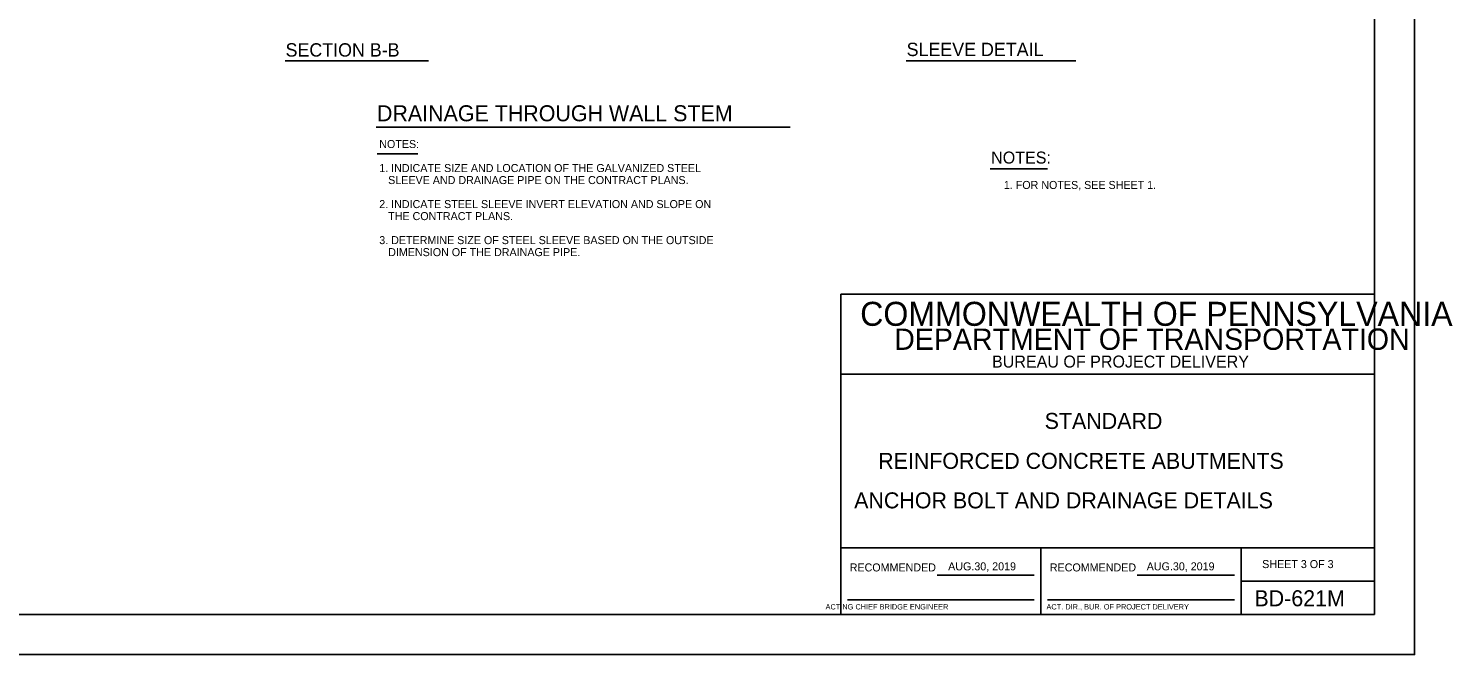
# Model space of a CAD drawing. Extents: x 235 to 2276, y 116 to 1308.
# Drawn here: x 1742 to 2276, y 710 to 945 of the extents above; entities that cross this region are included whole.
import ezdxf

# ---------------------------------------------------------------- set-up
doc = ezdxf.new("R2010")
doc.units = 0
doc.layers.add('1', color=7, linetype='Continuous')
doc.layers.add('PLT-BNDY', color=7, linetype='Continuous')

msp = doc.modelspace()

# ---------------------------------------------------------------- linework, layer by layer
at = {"layer": '1'}
for p, q in [((2246.42, 1289.41), (2246.42, 725.41)), ((1838.13, 932.78), (1891.85, 932.78)), ((2070.9, 932.78), (2134.5, 932.78)), ((1872.24, 907.91), (2027.46, 907.91)), ((1872.72, 897.95), (1887.85, 897.95)), ((2102.37, 892.39), (2123.91, 892.39)), ((2246.42, 845.41), (2046.42, 845.41)), ((2046.42, 845.41), (2046.42, 725.41)), ((2246.42, 725.41), (2246.42, 845.41)), ((2246.42, 815.41), (2046.42, 815.41)), ((2246.42, 750.41), (2046.42, 750.41)), ((2121.42, 725.41), (2121.42, 750.41)), ((2196.42, 750.41), (2196.42, 725.41)), ((2082.51, 740.13), (2118.92, 740.13)), ((2157.51, 740.13), (2193.92, 740.13)), ((2196.42, 737.91), (2246.42, 737.91)), ((2048.92, 730.91), (2118.92, 730.91)), ((2123.92, 730.91), (2193.92, 730.91)), ((2246.42, 725.41), (1460.42, 725.41)), ((2046.42, 725.41), (2246.42, 725.41))]:
    msp.add_line(p, q, dxfattribs=at)
at = {"layer": 'PLT-BNDY'}
msp.add_lwpolyline([(1420.42, 1304.41), (2261.42, 1304.41), (2261.42, 710.41), (1420.42, 710.41)], close=True, dxfattribs=at)

# ---------------------------------------------------------------- texts
at = {"layer": '1'}
for s, height, p in [('SECTION B-B', 5, (1838.33, 934.41)), ('SLEEVE DETAIL', 5, (2071.08, 934.6)), ('DRAINAGE THROUGH WALL STEM', 6, (1872.58, 910.17)), ('NOTES:', 3, (1873.44, 900.15)), ('NOTES:', 4.5, (2102.75, 894.33)), ('1. INDICATE SIZE AND LOCATION OF THE GALVANIZED STEEL', 3, (1873.44, 891.15)), ('   SLEEVE AND DRAINAGE PIPE ON THE CONTRACT PLANS.', 3, (1873.44, 886.65)), ('1. FOR NOTES, SEE SHEET 1.', 3, (2107.51, 884.82)), ('2. INDICATE STEEL SLEEVE INVERT ELEVATION AND SLOPE ON', 3, (1873.44, 877.65)), ('   THE CONTRACT PLANS.', 3, (1873.44, 873.15)), ('3. DETERMINE SIZE OF STEEL SLEEVE BASED ON THE OUTSIDE', 3, (1873.44, 864.15)), ('   DIMENSION OF THE DRAINAGE PIPE.', 3, (1873.44, 859.65)), ('COMMONWEALTH OF PENNSYLVANIA', 9, (2053.67, 833.54)), ('DEPARTMENT OF TRANSPORTATION', 8.0002, (2066.42, 824.54)), ('BUREAU OF PROJECT DELIVERY', 4.5, (2103.08, 817.91)), ('STANDARD', 6, (2122.8, 794.91)), ('REINFORCED CONCRETE ABUTMENTS', 6, (2060.4, 779.96)), ('ANCHOR BOLT AND DRAINAGE DETAILS', 6, (2051.42, 765.16)), ('RECOMMENDED', 3, (2049.75, 741.54)), ('AUG.30, 2019', 3, (2086.64, 741.94)), ('RECOMMENDED', 3, (2124.75, 741.54)), ('AUG.30, 2019', 3, (2161.05, 741.94)), ('SHEET 3 OF 3', 3, (2204.33, 742.79)), ('BD-621M', 6, (2201.42, 728.48)), ('       ACTING CHIEF BRIDGE ENGINEER', 2.0002, (2035.32, 727.29)), ('ACT. DIR., BUR. OF PROJECT DELIVERY', 2.0002, (2123.48, 727.29))]:
    msp.add_text(s, height=height, dxfattribs=at).set_placement(p)

doc.saveas('drawing.dxf')
